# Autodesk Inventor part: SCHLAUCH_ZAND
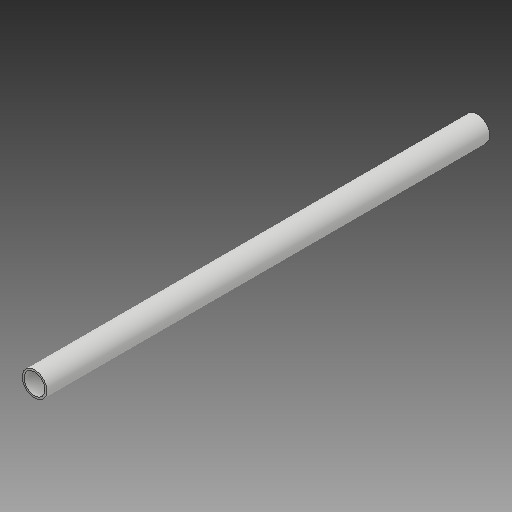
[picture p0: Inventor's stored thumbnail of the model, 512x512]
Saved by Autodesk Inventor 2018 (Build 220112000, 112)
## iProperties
Created: 2019-01
Part Number: SCHLAUCH_ZAND
Material: Generisch
Document SubType Name: Modeling
Designer: zand
Density: 1 g/cm^3
Appearance: Vorgabe
Author: zand
Revision Number: 5LAST_VERSION
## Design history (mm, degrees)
feature "Basis1"
node "Volumenkörper1"
